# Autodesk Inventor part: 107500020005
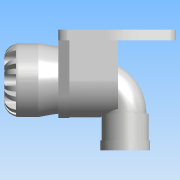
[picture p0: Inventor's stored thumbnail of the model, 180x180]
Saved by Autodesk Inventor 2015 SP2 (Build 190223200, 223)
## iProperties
Created: 2017-01
Part Number: 107500020005
Material: PVC-Piping
Description: PLASSON WALL PLATE ELBOW 20X1/2" SERIES 1
Document SubType Name: Modeling
Designer: Кирилл
Mass: 122.736 g
Surface Area: 365.546 cm^2
Volume: 87.6688 cm^3
Density: 1.4 g/cm^3
Appearance: Smooth - White
Author: KIM
Author: naamad
Title: SR1-ELBOW-BRACKET-20-CAT
Organization: PLASSON
Sending System: PRO/ENGINEER BY PARAMETRIC TECHNOLOGY CORPORATION, 2014000
Preprocessor: PRO/ENGINEER BY PARAMETRIC TECHNOLOGY CORPORATION, 2014000
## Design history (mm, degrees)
derived "1075.ipt"
feature "Solid1::1075.ipt"
feature "Solid8::1075.ipt"
feature "Solid11::1075.ipt"
tag "TaggingFeature1"
body "Solid1"
body "Solid2"
body "Solid3"
other parameters: "d4" = 41, "d5" = 25, "d6" = 18.9, "d7" = 45, "d9" = 36.08, "d13" = 3.96, "d14" = 7.92, "d24" = 39, "d26" = 67, "d29" = 23.47506, "d31" = 0, "d32" = 0, "d39" = 6.4, "d41" = 6.4, "d42" = 0, "d44" = 360 deg, "d46" = 8 deg, "d47" = 8 deg, "d48" = 0.4, "d49" = 0.4, "d51" = 0, "d53" = 360 deg, "d55" = 0.2, "d61" = 2, "d65" = 6.30247, "d69" = 90 deg, "d71" = 4.658, "d72" = 0, "d73" = 0, "d74" = 5.5, "d78" = 28, "d79" = 36.5, "d80" = 95, "d81" = 6, "d82" = 0, "d83" = 6, "d84" = 0, "d87" = 27, "d88" = 0, "d89" = 27, "d90" = 0, "d91" = 28, "d93" = 95, "d94" = 36.5, "d95" = 6, "d96" = 0, "d98" = 6, "d99" = 0, "d100" = 4.5, "d101" = 19, "d102" = 29, "d103" = 0, "d105" = 0, "d107" = 0, "d108" = 18.631, "d109" = 3.7262, "d110" = 0.74524, "d111" = 17, "d112" = 20.4, "d113" = 16.7679, "d114" = 5.66667, "Rp_" = 18.631, "E_" = 41, "l_" = 45, "l_2" = 17, "A_" = 67, "A_1" = 39, "A_2" = 28, "L_" = 73, "H_" = 95, "d30" = 26.0834, "d37" = 25, "d38" = 41, "d40" = 8
